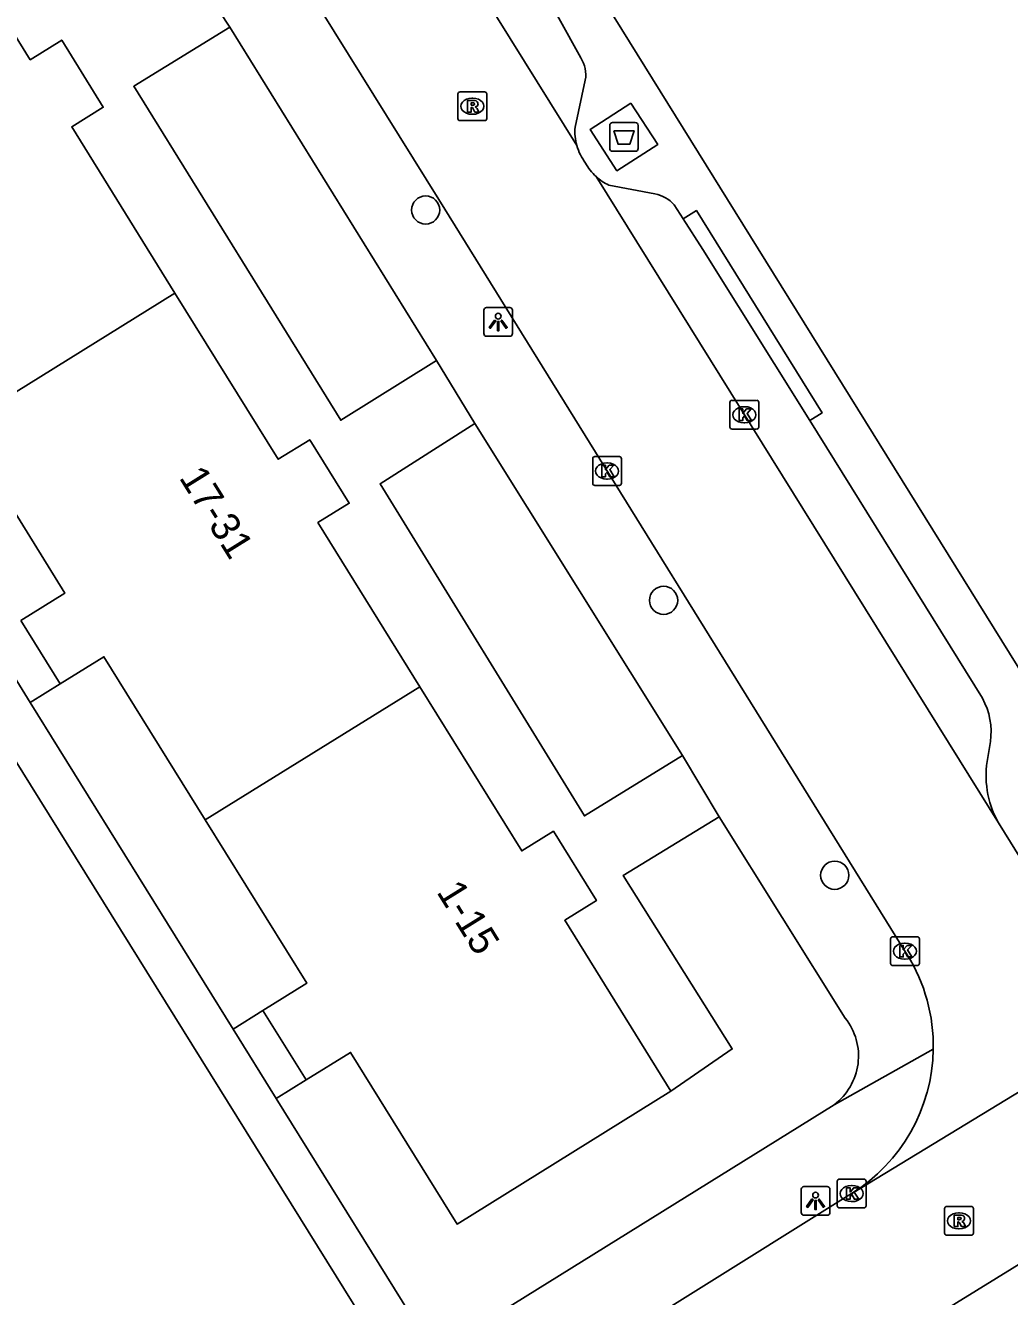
# Model space of a CAD drawing. Extents: x 160037 to 160839, y 385326 to 386441.
# Drawn here: x 160299.47 to 160333.65, y 386174.41 to 386218.54 of the extents above; entities that cross this region are included whole.
import ezdxf

# ---------------------------------------------------------------- set-up
doc = ezdxf.new("R2010")
doc.units = 0
for name, color, linetype in [('IMGEO_Afval_apart_plaats', 7, 'Continuous'), ('IMGEO_Boom', 7, 'Continuous'), ('IMGEO_Kolk', 7, 'Continuous'), ('IMGEO_Lichtpunt', 7, 'Continuous'), ('IMGEO_Pand', 7, 'Continuous'), ('IMGEO_Pand_nummerreeks', 7, 'Continuous'), ('IMGEO_Rijbaan_lokaal_open', 7, 'Continuous'), ('IMGEO_Rioolput', 7, 'Continuous'), ('IMGEO_Voetpad_gesloten', 7, 'Continuous'), ('IMGEO_Voetpad_op_trap', 7, 'Continuous'), ('IMGEO_Voetpad_open', 7, 'Continuous')]:
    doc.layers.add(name, color=color, linetype=linetype)

msp = doc.modelspace()

# ---------------------------------------------------------------- linework, layer by layer
at = {"layer": 'IMGEO_Afval_apart_plaats'}
for p, q in [((160319.761, 386214.265), (160319.761, 386215.065)), ((160319.761, 386215.065), (160319.761, 386214.265)), ((160319.861, 386215.165), (160320.651, 386215.165)), ((160320.651, 386215.165), (160319.861, 386215.165)), ((160320.751, 386215.065), (160320.751, 386214.265)), ((160320.751, 386214.265), (160320.751, 386215.065)), ((160320.651, 386214.165), (160319.861, 386214.165)), ((160319.861, 386214.165), (160320.651, 386214.165))]:
    msp.add_line(p, q, dxfattribs=at)
msp.add_lwpolyline([(160319.904, 386214.879), (160320.608, 386214.879), (160320.459, 386214.409), (160320.053, 386214.409), (160319.904, 386214.879)], dxfattribs=at)
for centre, start, end in [((160319.861, 386215.065), 90, 180), ((160319.861, 386215.065), 90, 180), ((160320.651, 386215.065), 0, 90), ((160320.651, 386215.065), 360, 90), ((160319.861, 386214.265), 180, 270), ((160319.861, 386214.265), 180, 270), ((160320.651, 386214.265), 270, 0), ((160320.651, 386214.265), 270, 0)]:
    msp.add_arc(centre, 0.1, start, end, dxfattribs=at)
at = {"layer": 'IMGEO_Boom'}
for centre in [(160313.371, 386212.128), (160321.633, 386198.577), (160327.575, 386189.032)]:
    msp.add_circle(centre, 0.489, dxfattribs=at)
at = {"layer": 'IMGEO_Kolk'}
for p, q in [((160324.012, 386205.52), (160324.864, 386205.52)), ((160323.937, 386204.594), (160323.937, 386205.446)), ((160324.425, 386205.3), (160324.45, 386205.3)), ((160324.938, 386205.446), (160324.938, 386204.594)), ((160324.448, 386204.74), (160324.423, 386204.74)), ((160324.864, 386204.52), (160324.012, 386204.52)), ((160319.17, 386202.64), (160319.17, 386203.492)), ((160319.245, 386203.566), (160320.097, 386203.566)), ((160319.658, 386203.346), (160319.683, 386203.346)), ((160320.171, 386203.492), (160320.171, 386202.64)), ((160320.097, 386202.566), (160319.245, 386202.566)), ((160319.681, 386202.786), (160319.656, 386202.786)), ((160329.511, 386185.971), (160329.511, 386186.823)), ((160329.586, 386186.897), (160330.438, 386186.897)), ((160329.999, 386186.677), (160330.024, 386186.677)), ((160330.512, 386186.823), (160330.512, 386185.971)), ((160330.022, 386186.117), (160329.997, 386186.117)), ((160330.438, 386185.897), (160329.586, 386185.897)), ((160327.663, 386177.557), (160327.663, 386178.409)), ((160327.738, 386178.483), (160328.59, 386178.483)), ((160328.151, 386178.263), (160328.176, 386178.263)), ((160328.664, 386178.409), (160328.664, 386177.557)), ((160328.174, 386177.703), (160328.149, 386177.703)), ((160328.59, 386177.483), (160327.738, 386177.483))]:
    msp.add_line(p, q, dxfattribs=at)
for points in [[(160324.012, 386205.52), (160324.864, 386205.52)], [(160323.937, 386204.594), (160323.937, 386205.446)], [(160324.258, 386205.22), (160324.381, 386205.22), (160324.381, 386205.069), (160324.511, 386205.22), (160324.675, 386205.22), (160324.529, 386205.069), (160324.682, 386204.82), (160324.53, 386204.82), (160324.445, 386204.984), (160324.381, 386204.917), (160324.381, 386204.82), (160324.258, 386204.82), (160324.258, 386205.22)], [(160324.938, 386205.446), (160324.938, 386204.594)], [(160324.864, 386204.52), (160324.012, 386204.52)], [(160319.17, 386202.64), (160319.17, 386203.492)], [(160319.245, 386203.566), (160320.097, 386203.566)], [(160319.491, 386203.266), (160319.614, 386203.266), (160319.614, 386203.115), (160319.744, 386203.266), (160319.908, 386203.266), (160319.762, 386203.115), (160319.915, 386202.866), (160319.763, 386202.866), (160319.678, 386203.03), (160319.614, 386202.963), (160319.614, 386202.866), (160319.491, 386202.866), (160319.491, 386203.266)], [(160320.171, 386203.492), (160320.171, 386202.64)], [(160320.097, 386202.566), (160319.245, 386202.566)], [(160329.511, 386185.971), (160329.511, 386186.823)], [(160329.586, 386186.897), (160330.438, 386186.897)], [(160329.832, 386186.597), (160329.955, 386186.597), (160329.955, 386186.446), (160330.085, 386186.597), (160330.249, 386186.597), (160330.103, 386186.446), (160330.256, 386186.197), (160330.104, 386186.197), (160330.019, 386186.361), (160329.955, 386186.294), (160329.955, 386186.197), (160329.832, 386186.197), (160329.832, 386186.597)], [(160330.512, 386186.823), (160330.512, 386185.971)], [(160330.438, 386185.897), (160329.586, 386185.897)], [(160327.663, 386177.557), (160327.663, 386178.409)], [(160327.738, 386178.483), (160328.59, 386178.483)], [(160327.984, 386178.183), (160328.107, 386178.183), (160328.107, 386178.032), (160328.237, 386178.183), (160328.401, 386178.183), (160328.255, 386178.032), (160328.408, 386177.783), (160328.256, 386177.783), (160328.171, 386177.947), (160328.107, 386177.88), (160328.107, 386177.783), (160327.984, 386177.783), (160327.984, 386178.183)], [(160328.664, 386178.409), (160328.664, 386177.557)], [(160328.59, 386177.483), (160327.738, 386177.483)]]:
    msp.add_lwpolyline(points, dxfattribs=at)
for centre, start, end in [((160324.014, 386205.444), 91.552, 178.448), ((160324.014, 386205.444), 91.552, 178.448), ((160324.862, 386205.444), 1.552, 88.448), ((160324.862, 386205.444), 1.552, 88.448), ((160324.014, 386204.596), 181.552, 268.448), ((160324.014, 386204.596), 181.552, 268.448), ((160324.862, 386204.596), 271.552, 358.448), ((160324.862, 386204.596), 271.552, 358.448), ((160319.247, 386203.49), 91.552, 178.448), ((160319.247, 386203.49), 91.552, 178.448), ((160320.095, 386203.49), 1.552, 88.448), ((160320.095, 386203.49), 1.552, 88.448), ((160319.247, 386202.642), 181.552, 268.448), ((160319.247, 386202.642), 181.552, 268.448), ((160320.095, 386202.642), 271.552, 358.448), ((160320.095, 386202.642), 271.552, 358.448), ((160329.588, 386186.821), 91.552, 178.448), ((160329.588, 386186.821), 91.552, 178.448), ((160330.436, 386186.821), 1.552, 88.448), ((160330.436, 386186.821), 1.552, 88.448), ((160329.588, 386185.973), 181.552, 268.448), ((160329.588, 386185.973), 181.552, 268.448), ((160330.436, 386185.973), 271.552, 358.448), ((160330.436, 386185.973), 271.552, 358.448), ((160327.74, 386178.407), 91.552, 178.448), ((160327.74, 386178.407), 91.552, 178.448), ((160328.588, 386178.407), 1.552, 88.448), ((160328.588, 386178.407), 1.552, 88.448), ((160327.74, 386177.559), 181.552, 268.448), ((160327.74, 386177.559), 181.552, 268.448), ((160328.588, 386177.559), 271.552, 358.448), ((160328.588, 386177.559), 271.552, 358.448)]:
    msp.add_arc(centre, 0.0765, start, end, dxfattribs=at)
for centre, major_axis, ratio, start_param, end_param in [((160324.424, 386205.02), (-0.387, 0.002), 0.722429, 4.712389, 7.853982), ((160324.449, 386205.02), (-0.39, 0.002), 0.717154, 1.570796, 4.712389), ((160319.657, 386203.066), (-0.387, 0.002), 0.722429, 4.712389, 7.853982), ((160319.682, 386203.066), (-0.39, 0.002), 0.717154, 1.570796, 4.712389), ((160329.998, 386186.397), (-0.387, 0.002), 0.722429, 4.712389, 7.853982), ((160330.023, 386186.397), (-0.39, 0.002), 0.717154, 1.570796, 4.712389), ((160328.15, 386177.983), (-0.387, 0.002), 0.722429, 4.712389, 7.853982), ((160328.175, 386177.983), (-0.39, 0.002), 0.717154, 1.570796, 4.712389)]:
    msp.add_ellipse(centre, major_axis=major_axis, ratio=ratio, start_param=start_param, end_param=end_param, dxfattribs=at)
at = {"layer": 'IMGEO_Lichtpunt'}
for p, q in [((160315.391, 386208.645), (160315.391, 386207.838)), ((160315.391, 386208.645), (160315.391, 386207.838)), ((160316.293, 386208.74), (160315.485, 386208.74)), ((160316.293, 386208.74), (160315.485, 386208.74)), ((160316.387, 386207.838), (160316.387, 386208.645)), ((160316.387, 386207.838), (160316.387, 386208.645)), ((160315.485, 386207.744), (160316.293, 386207.744)), ((160315.485, 386207.744), (160316.293, 386207.744)), ((160326.411, 386178.13), (160326.411, 386177.323)), ((160326.411, 386178.13), (160326.411, 386177.323)), ((160327.313, 386178.225), (160326.505, 386178.225)), ((160327.313, 386178.225), (160326.505, 386178.225)), ((160327.407, 386177.323), (160327.407, 386178.13)), ((160327.407, 386177.323), (160327.407, 386178.13)), ((160326.505, 386177.229), (160327.313, 386177.229)), ((160326.505, 386177.229), (160327.313, 386177.229))]:
    msp.add_line(p, q, dxfattribs=at)
for points in [[(160315.765, 386208.309), (160315.804, 386208.281), (160315.616, 386208.019), (160315.578, 386208.046), (160315.765, 386208.309)], [(160315.867, 386208.261), (160315.914, 386208.261), (160315.914, 386207.939), (160315.867, 386207.939), (160315.867, 386208.261)], [(160315.977, 386208.281), (160316.015, 386208.308), (160316.202, 386208.046), (160316.163, 386208.018), (160315.977, 386208.281)], [(160326.785, 386177.794), (160326.824, 386177.766), (160326.636, 386177.504), (160326.598, 386177.531), (160326.785, 386177.794)], [(160326.887, 386177.746), (160326.934, 386177.746), (160326.934, 386177.424), (160326.887, 386177.424), (160326.887, 386177.746)], [(160326.997, 386177.766), (160327.035, 386177.793), (160327.222, 386177.531), (160327.183, 386177.503), (160326.997, 386177.766)]]:
    msp.add_lwpolyline(points, dxfattribs=at)
for centre in [(160315.89, 386208.443), (160326.91, 386177.928)]:
    msp.add_circle(centre, 0.0994, dxfattribs=at)
for centre, start, end in [((160315.485, 386208.645), 90, 180), ((160315.485, 386208.645), 90, 180), ((160316.293, 386208.645), 0, 90), ((160316.293, 386208.645), 0, 90), ((160315.485, 386207.838), 180, 270), ((160315.485, 386207.838), 180, 270), ((160316.293, 386207.838), 270, 0), ((160316.293, 386207.838), 270, 360), ((160326.505, 386178.13), 90, 180), ((160326.505, 386178.13), 90, 180), ((160327.313, 386178.13), 0, 90), ((160327.313, 386178.13), 0, 90), ((160326.505, 386177.323), 180, 270), ((160326.505, 386177.323), 180, 270), ((160327.313, 386177.323), 270, 0), ((160327.313, 386177.323), 270, 360)]:
    msp.add_arc(centre, 0.0946, start, end, dxfattribs=at)
at = {"layer": 'IMGEO_Pand'}
for points in [[(160304.668, 386209.246), (160301.085, 386215.019), (160302.179, 386215.698), (160300.735, 386218.025), (160299.642, 386217.346), (160296.083, 386223.081)], [(160304.668, 386209.246), (160297.243, 386204.638)], [(160313.169, 386195.575), (160309.632, 386201.274), (160310.716, 386201.947), (160309.347, 386204.154), (160308.251, 386203.473), (160304.668, 386209.246)], [(160299.312, 386197.878), (160300.847, 386198.83), (160297.243, 386204.638)], [(160300.679, 386195.676), (160299.312, 386197.878)], [(160305.72, 386190.952), (160302.202, 386196.621), (160300.679, 386195.676)], [(160305.72, 386190.952), (160313.169, 386195.575)], [(160321.888, 386181.533), (160318.202, 386187.472), (160319.298, 386188.152), (160317.805, 386190.558), (160316.705, 386189.876), (160313.169, 386195.575)], [(160307.722, 386184.339), (160309.24, 386185.281), (160305.72, 386190.952)], [(160309.22, 386181.925), (160307.722, 386184.339)], [(160321.888, 386181.533), (160314.462, 386176.925), (160310.764, 386182.883), (160309.22, 386181.925)]]:
    msp.add_lwpolyline(points, dxfattribs=at)
at = {"layer": 'IMGEO_Rijbaan_lokaal_open'}
for points in [[(160296.637, 386240.069), (160313.825, 386212.492), (160330.091, 386186.273)], [(160318.62, 386214.364), (160302.477, 386240.29)], [(160333.315, 386190.762), (160319.29, 386213.287)], [(160334.54, 386188.784), (160333.315, 386190.762)], [(160328.161, 386177.98), (160328.191, 386177.996), (160342.516, 386186.712), (160342.893, 386187.018)], [(160340.53, 386179.543), (160340.383, 386179.474), (160326.552, 386170.947), (160326.329, 386170.774)], [(160304.012, 386162.957), (160316.882, 386170.942), (160328.161, 386177.98)]]:
    msp.add_lwpolyline(points, dxfattribs=at)
for centre, radius, start, end in [((160320.392, 386214.864), 1.841, 195.7577, 216.9177), ((160320.534, 386214.645), 1.841, 208.7918, 227.5119), ((160324.978, 386183.096), 6.019, 358.9949, 31.8606), ((160324.97, 386183.094), 6.028, 301.9631, 359.0113)]:
    msp.add_arc(centre, radius, start, end, dxfattribs=at)
at = {"layer": 'IMGEO_Rioolput'}
for p, q in [((160314.492, 386215.304), (160314.492, 386216.156)), ((160314.567, 386216.23), (160315.419, 386216.23)), ((160315.493, 386216.156), (160315.493, 386215.304)), ((160314.98, 386216.01), (160315.005, 386216.01)), ((160315.419, 386215.23), (160314.567, 386215.23)), ((160315.003, 386215.45), (160314.978, 386215.45)), ((160331.388, 386176.611), (160331.388, 386177.463)), ((160331.463, 386177.537), (160332.315, 386177.537)), ((160331.876, 386177.317), (160331.901, 386177.317)), ((160332.389, 386177.463), (160332.389, 386176.611)), ((160332.315, 386176.537), (160331.463, 386176.537)), ((160331.899, 386176.757), (160331.874, 386176.757))]:
    msp.add_line(p, q, dxfattribs=at)
for points in [[(160314.492, 386215.304), (160314.492, 386216.156)], [(160314.567, 386216.23), (160315.419, 386216.23)], [(160315.493, 386216.156), (160315.493, 386215.304)], [(160315.081, 386215.928), (160314.829, 386215.93), (160314.829, 386215.53)], [(160314.829, 386215.53), (160314.953, 386215.53), (160314.953, 386215.692), (160314.964, 386215.692)], [(160315.007, 386215.849), (160314.953, 386215.849), (160314.953, 386215.768)], [(160314.953, 386215.768), (160315.005, 386215.768)], [(160315.011, 386215.663), (160315.082, 386215.53), (160315.222, 386215.53), (160315.157, 386215.656)], [(160315.419, 386215.23), (160314.567, 386215.23)], [(160331.388, 386176.611), (160331.388, 386177.463)], [(160331.463, 386177.537), (160332.315, 386177.537)], [(160331.977, 386177.235), (160331.725, 386177.237), (160331.725, 386176.837)], [(160332.389, 386177.463), (160332.389, 386176.611)], [(160331.725, 386176.837), (160331.849, 386176.837), (160331.849, 386176.999), (160331.86, 386176.999)], [(160331.903, 386177.156), (160331.849, 386177.156), (160331.849, 386177.075)], [(160331.849, 386177.075), (160331.901, 386177.075)], [(160331.907, 386176.97), (160331.978, 386176.837), (160332.118, 386176.837), (160332.053, 386176.963)], [(160332.315, 386176.537), (160331.463, 386176.537)]]:
    msp.add_lwpolyline(points, dxfattribs=at)
for centre, radius, start, end in [((160314.569, 386216.154), 0.0765, 91.552, 178.448), ((160314.569, 386216.154), 0.0765, 91.552, 178.448), ((160315.417, 386216.154), 0.0765, 1.552, 88.448), ((160315.417, 386216.154), 0.0765, 1.552, 88.448), ((160314.963, 386215.639), 0.0533, 26.0293, 88.6989), ((160314.989, 386215.957), 0.19, 274.7715, 282.9687), ((160315.013, 386215.753), 0.0964, 77.0061, 93.1865), ((160315.027, 386215.81), 0.0378, 276.6634, 79.6772), ((160315.08, 386215.818), 0.109, 350.3612, 89.416), ((160315.078, 386215.818), 0.112, 277.5842, 350.9817), ((160315.062, 386215.603), 0.108, 29.5134, 73.7905), ((160314.569, 386215.306), 0.0765, 181.552, 268.448), ((160314.569, 386215.306), 0.0765, 181.552, 268.448), ((160315.417, 386215.306), 0.0765, 271.552, 358.448), ((160315.417, 386215.306), 0.0765, 271.552, 358.448), ((160331.465, 386177.461), 0.0765, 91.552, 178.448), ((160331.465, 386177.461), 0.0765, 91.552, 178.448), ((160331.976, 386177.125), 0.109, 350.3612, 89.416), ((160332.313, 386177.461), 0.0765, 1.552, 88.448), ((160332.313, 386177.461), 0.0765, 1.552, 88.448), ((160331.859, 386176.946), 0.0533, 26.0293, 88.6989), ((160331.885, 386177.264), 0.19, 274.7715, 282.9687), ((160331.909, 386177.06), 0.0964, 77.0061, 93.1865), ((160331.923, 386177.117), 0.0378, 276.6634, 79.6772), ((160331.974, 386177.125), 0.112, 277.5842, 350.9817), ((160331.958, 386176.91), 0.108, 29.5134, 73.7905), ((160331.465, 386176.613), 0.0765, 181.552, 268.448), ((160331.465, 386176.613), 0.0765, 181.552, 268.448), ((160332.313, 386176.613), 0.0765, 271.552, 358.448), ((160332.313, 386176.613), 0.0765, 271.552, 358.448)]:
    msp.add_arc(centre, radius, start, end, dxfattribs=at)
for centre, major_axis, ratio, start_param, end_param in [((160314.979, 386215.73), (-0.387, 0.002), 0.722429, 4.712389, 7.853982), ((160315.004, 386215.73), (-0.39, 0.002), 0.717154, 1.570796, 4.712389), ((160331.875, 386177.037), (-0.387, 0.002), 0.722429, 4.712389, 7.853982), ((160331.9, 386177.037), (-0.39, 0.002), 0.717154, 1.570796, 4.712389)]:
    msp.add_ellipse(centre, major_axis=major_axis, ratio=ratio, start_param=start_param, end_param=end_param, dxfattribs=at)
at = {"layer": 'IMGEO_Voetpad_gesloten'}
msp.add_lwpolyline([(160320.497, 386215.84), (160321.427, 386214.404), (160320.014, 386213.489), (160319.084, 386214.925), (160320.497, 386215.84)], dxfattribs=at)
at = {"layer": 'IMGEO_Voetpad_op_trap'}
for points in [[(160299.637, 386195.028), (160300.679, 386195.676)], [(160307.722, 386184.339), (160306.682, 386183.693)], [(160308.182, 386181.28), (160309.22, 386181.925)]]:
    msp.add_lwpolyline(points, dxfattribs=at)
at = {"layer": 'IMGEO_Voetpad_open'}
for points in [[(160337.312, 386190.843), (160304.123, 386244.251)], [(160306.126, 386237.9), (160317.999, 386218.787), (160318.758, 386217.412)], [(160275.723, 386230.616), (160312.412, 386171.653)], [(160305.162, 386220.629), (160306.568, 386218.474)], [(160313.752, 386206.898), (160310.423, 386204.827), (160303.238, 386216.424), (160306.568, 386218.474)], [(160306.568, 386218.474), (160313.752, 386206.898)], [(160318.914, 386216.634), (160318.557, 386215.007)], [(160319.733, 386212.99), (160321.331, 386212.684)], [(160321.995, 386212.306), (160322.309, 386211.819)], [(160322.309, 386211.819), (160322.771, 386212.107), (160327.137, 386205.085), (160326.706, 386204.817)], [(160322.991, 386210.759), (160322.309, 386211.819)], [(160326.706, 386204.817), (160322.991, 386210.759)], [(160313.752, 386206.898), (160315.078, 386204.713)], [(160322.284, 386193.185), (160318.885, 386191.095), (160311.788, 386202.622), (160315.078, 386204.713)], [(160315.078, 386204.713), (160322.284, 386193.185)], [(160326.706, 386204.817), (160332.704, 386195.176)], [(160298.269, 386197.229), (160299.637, 386195.028)], [(160299.637, 386195.028), (160306.682, 386183.693)], [(160332.978, 386193.672), (160332.867, 386192.983)], [(160322.284, 386193.185), (160323.561, 386191.066)], [(160323.561, 386191.066), (160320.231, 386189.03), (160324.014, 386183.004), (160321.888, 386181.533)], [(160323.561, 386191.066), (160327.936, 386184.073)], [(160306.682, 386183.693), (160308.182, 386181.28)], [(160327.55, 386181.067), (160330.997, 386182.99)], [(160308.182, 386181.28), (160313.676, 386172.439)], [(160327.55, 386181.067), (160313.676, 386172.439)]]:
    msp.add_lwpolyline(points, dxfattribs=at)
for centre, radius, start, end in [((160317.851, 386216.825), 1.08, 349.7879, 32.8887), ((160320.389, 386214.862), 1.838, 175.4742, 195.7176), ((160320.519, 386214.641), 1.828, 227.7743, 244.5476), ((160321.157, 386211.605), 1.093, 39.8825, 80.8138), ((160330.565, 386194.009), 2.437, 352.0445, 28.6054), ((160336.139, 386192.487), 3.309, 171.3859, 211.4224), ((160326.298, 386182.756), 2.102, 306.5541, 38.8113)]:
    msp.add_arc(centre, radius, start, end, dxfattribs=at)

# ---------------------------------------------------------------- texts
at = {"layer": 'IMGEO_Pand_nummerreeks'}
for s, rotation, p in [('17-31', 301.873, (160304.789, 386202.839)), ('1-15', 301.8386, (160313.729, 386188.455))]:
    msp.add_text(s, height=1, rotation=rotation, dxfattribs=at).set_placement(p)

doc.saveas('drawing.dxf')
